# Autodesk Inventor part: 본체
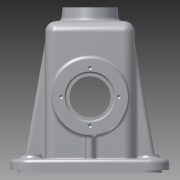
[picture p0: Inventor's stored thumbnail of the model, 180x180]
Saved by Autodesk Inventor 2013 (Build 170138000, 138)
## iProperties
Created: 2016-01
Part Number: 본체
Material: 알루미늄 6061
Document SubType Name: Modeling
Designer: User
Mass: 857.084 g
Surface Area: 924.112 cm^2
Volume: 316.267 cm^3
Density: 2.71 g/cm^3
Author: User
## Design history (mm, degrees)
sketch "스케치1"
  geometry: L1 (-32.5, 32.5)-(32.5, 32.5); L2 (32.5, 32.5)-(32.5, -32.5); L3 (32.5, -32.5)-(-32.5, -32.5); L4 (-32.5, -32.5)-(-32.5, 32.5); L5 (-32.5, 32.5)-(32.5, -32.5); L6 (32.5, 32.5)-(-32.5, -32.5); 1 further point
  constraints: 12 end point, 2 midpoint, 2 parallel, 1 horizontal, 1 perpendicular
  dimensions: "d0" = 65 distance of L2.end L3.end; "d1" = 65 distance of L1.end L2.end
extrude "돌출1" new body sketch "스케치1" distance "d2" = 110; taper "d3" = 0 deg
sketch "스케치2"
  geometry: L1 (-57.5, 65)-(57.5, 65); L2 (57.5, 65)-(57.5, -65); L3 (57.5, -65)-(-57.5, -65); L4 (-57.5, -65)-(-57.5, 65); L5 (-57.5, 65)-(57.5, -65); L6 (57.5, 65)-(-57.5, -65); 1 further point
  constraints: 12 end point, 2 midpoint, 2 parallel, 1 horizontal, 1 perpendicular
  dimensions: "d4" = 115 distance of L2.end L3.end; "d5" = 130 distance of L1.end L2.end
extrude "돌출2" join sketch "스케치2" distance "d6" = 10; taper "d7" = 0 deg
sketch "스케치3"
  geometry: L1 (-57.5, 65)-(57.5, 65) reference; L2 (-57.5, -65)-(-57.5, 65) reference; L3 (57.5, -65)-(-57.5, -65) reference; L4 (57.5, 65)-(57.5, -65) reference; L5 (52.5, 60)-(-52.5, 60); L6 (-52.5, 60)-(-52.5, -60); L7 (-52.5, -60)-(52.5, -60); L8 (52.5, -60)-(52.5, 60); 1 further point
  constraints: 8 end point, 3 other
  dimensions: "d8" = 5 distance between parallel lines of L5 L1
extrude "돌출3" cut sketch "스케치3" distance "d9" = 2; taper "d10" = 0 deg
fillet "모깎기1" dims "d11" = 15
fillet "모깎기2" dims "d12" = 15
sketch "스케치4"
  geometry: L1 (-65, 10)-(-32.5, 10) reference; L2 (-32.5, 10)-(-32.5, 110) reference; L3 (-32.5, 110)-(32.5, 110) reference; L4 (32.5, 110)-(32.5, 10) reference; L5 (32.5, 10)-(65, 10) reference; L6 (65, 10)-(65, 2) reference; L7 (65, 2)-(60, 2) reference; L8 (60, 2)-(60, 0) reference; L9 (60, 0)-(-60, 0) reference; L10 (-60, 0)-(-60, 2) reference; L11 (-60, 2)-(-65, 2) reference; L12 (-65, 2)-(-65, 10) reference; L13 (27.5, 105)-(27.5, 0); L14 (27.5, 105)-(-27.5, 105); L15 (-27.5, 105)-(-27.5, 0); 1 further point
  constraints: 6 end point, 2 perpendicular, 2 point on line, 1 vertical
  dimensions: "d13" = 5 distance between parallel lines of L4 L13; "d14" = 5 distance between parallel lines of L2 L15; "d15" = 5 distance between parallel lines of L3 L14
extrude "돌출4" cut sketch "스케치4" stored distance "d16" = 55; taper "d17" = 0 deg
sketch "스케치5"
  geometry: L1 (0, 0)-(65, 0) reference; L2 (70, -110)-(-5, -110) reference; C1 r 27.5 at (32.5, -55); 2 further points
  constraints: 1 centre point, 1 midpoint, 1 vertical alignment
  dimensions: "d18" = 55 diameter of C1; "d19" = 55 distance from line of L2 C1.centre
extrude "돌출5" join sketch "스케치5" distance "d20" = 15; taper "d21" = 0 deg
sketch "스케치6"
  geometry: L1 (-52.742, 55)-(52.163, 55); L2 (-30.5, 72.5)-(-30.5, 70); L3 (30.5, 70)-(30.5, 72.5); L4 (-65, 10)-(-32.5, 10) reference; L5 (-32.5, 10)-(-32.5, 27.5) reference; L6 (-32.5, 27.5)-(-47.5, 27.5) reference; L7 (-47.5, 27.5)-(-47.5, 82.5) reference; L8 (-47.5, 82.5)-(-32.5, 82.5) reference; L9 (-32.5, 82.5)-(-32.5, 110) reference; L10 (-32.5, 110)-(32.5, 110) reference; L11 (32.5, 110)-(32.5, 82.5) reference; L12 (32.5, 82.5)-(47.5, 82.5) reference; L13 (47.5, 82.5)-(47.5, 27.5) reference; L14 (47.5, 27.5)-(32.5, 27.5) reference; L15 (32.5, 27.5)-(32.5, 10) reference; L16 (32.5, 10)-(65, 10) reference; L17 (65, 10)-(65, 2) reference; L18 (65, 2)-(60, 2) reference; L19 (60, 2)-(60, 0) reference; L20 (60, 0)-(27.5, 0) reference; L21 (27.5, 0)-(27.5, 105) reference; L22 (27.5, 105)-(-27.5, 105) reference; L23 (-27.5, 105)-(-27.5, 0) reference; L24 (-27.5, 0)-(-60, 0) reference; L25 (-60, 0)-(-60, 2) reference; L26 (-60, 2)-(-65, 2) reference; L27 (-65, 2)-(-65, 10) reference; L28 (-30.5, 72.5)-(-47.5, 72.5); L29 (30.5, 72.5)-(47.5, 72.5); L30 (-47.5, 72.5)-(-47.5, 55); L31 (47.5, 72.5)-(47.5, 55); L32 (-30.5, 70)-(-27.5, 70); L33 (-27.5, 70)-(-27.5, 55); L34 (30.5, 72.5)-(30.5, 70); L35 (30.5, 70)-(27.5, 70); L36 (27.5, 70)-(27.5, 55); L37 (-47.5, 55)-(-27.5, 55); L38 (27.5, 55)-(47.5, 55); 1 further point
  constraints: 28 end point, 8 point on line, 4 perpendicular, 2 collinear, 2 midpoint, 2 parallel, 1 horizontal
  dimensions: "d22" = 55 distance from line of point (0, 0) L1; "d23" = 35 diameter of L28 L1; "d25" = 17 distance of L2.start L28.end; "d26" = 17 distance of L3.end L29.end; "d27" = 61 distance between parallel lines of L2 L3; "d28" = 30 diameter of L32 L1
  node "절단 모서리 투영2"
revolve "회전1" stored, may be unused: angle "d29" = 90 deg
revolve "회전2" stored, may be unused: angle "d30" = 90 deg
sketch "스케치7"
  geometry: C1 r 20 at (0, 0); 1 further point
  constraints: 1 centre point, 1 coincident
  dimensions: "d31" = 40 diameter of C1
extrude "돌출6" join sketch "스케치7" distance "d32" = 10; taper "d33" = 0 deg
feature "면 기울기1" dims angle "d34" = 5 deg
sketch "스케치8"
  geometry: C1 r 20 at (0, 0) reference; C2 r 10.5 at (0, 0)
  constraints: 1 centre point, 1 coincident
  dimensions: "d35" = 21 diameter of C2
extrude "돌출7" cut sketch "스케치8" distance "d36" = 20.75; taper "d37" = 0 deg
sketch "스케치9" dims "d38" = 29
  geometry: C1 r 20 at (0, 0) reference; 2 further points
  constraints: 2 vertical alignment, 1 coincident, 2 other
hole "구멍1" sketch "스케치9" at (0, 14.5) diameter "d39" = 2.459; stored, may be unused: countersink angle "d43" = 90 deg, drill point angle "d45" = 118 deg; dims "d40" = 7, "d41" = 4, "d42" = 2, "d44" = 9
sketch "스케치10" dims "d49" = 42
  geometry: C1 r 27.5 at (0, 0) reference; 3 further points
  constraints: 2 horizontal alignment, 1 coincident, 2 other
hole "구멍2" sketch "스케치10" at (21, 0) diameter "d50" = 3.242; stored, may be unused: countersink angle "d54" = 90 deg, drill point angle "d56" = 118 deg; dims "d51" = 8, "d52" = 4, "d53" = 2, "d55" = 10
sketch "스케치11"
  geometry: L1 (27.5, 0)-(27.5, 105) reference; L2 (27.5, 105)-(10.5, 105) reference; L3 (10.5, 105)-(10.5, 120) reference; L4 (10.5, 120)-(13.27, 120) reference; L5 (13.27, 120)-(13.27, 111) reference; L6 (13.27, 111)-(14.5, 110.261) reference; L7 (14.5, 110.261)-(15.73, 111) reference; L8 (15.73, 111)-(15.73, 120) reference; L9 (15.73, 120)-(20, 120) reference; L10 (20, 120)-(20.875, 110) reference; L11 (20.875, 110)-(32.5, 110) reference; L12 (32.5, 110)-(32.5, 10) reference; L13 (32.5, 10)-(57.5, 10) reference; L14 (57.5, 10)-(57.5, 2) reference; L15 (57.5, 2)-(52.5, 2) reference; L16 (52.5, 2)-(52.5, 0) reference; L17 (52.5, 0)-(27.5, 0) reference; L18 (-52.5, 2)-(-57.5, 2) reference; L19 (-57.5, 2)-(-57.5, 10) reference; L20 (-57.5, 10)-(-32.5, 10) reference; L21 (-32.5, 10)-(-32.5, 110) reference; L22 (-32.5, 110)-(-20.875, 110) reference; L23 (-20.875, 110)-(-20, 120) reference; L24 (-20, 120)-(-15.73, 120) reference; L25 (-15.73, 120)-(-15.73, 111) reference; L26 (-15.73, 111)-(-14.5, 110.261) reference; L27 (-14.5, 110.261)-(-13.27, 111) reference; L28 (-13.27, 111)-(-13.27, 120) reference; L29 (-13.27, 120)-(-10.5, 120) reference; L30 (-10.5, 120)-(-10.5, 105) reference; L31 (-10.5, 105)-(-27.5, 105) reference; L32 (-27.5, 105)-(-27.5, 0) reference; L33 (-27.5, 0)-(-52.5, 0) reference; L34 (-52.5, 0)-(-52.5, 2) reference; L35 (-32.5, 95.069)-(-47.5, 10); L36 (47.5, 10)-(32.5, 95.069); 1 further point
  constraints: 4 end point, 4 point on line
  dimensions: "d60" = 10 deg angle of L35 L19; "d61" = 10 distance from line of L35.end L19; "d62" = 10 distance of L13.end L36.start; "d63" = 10 deg angle of L14 L36
  node "절단 모서리 투영3"
feature "리브1" dims "d64" = 1, "d65" = 10, "d66" = 0, "d67" = 0, "d68" = 1, "d69" = 1
feature "리브2" dims "d70" = 1, "d71" = 10, "d72" = 0, "d73" = 0, "d74" = 1, "d75" = 1
sketch "스케치12"
  geometry: L1 (-52.5, 45)-(-52.5, -45) reference; L2 (37.5, 60)-(-37.5, 60) reference; L3 (-27.5, 27.5)-(27.5, 27.5) reference; L4 (-42.5, 50)-(42.5, 50); L5 (-42.5, 50)-(-42.5, -50); C1 r 3 at (-42.5, 50); C2 r 3 at (42.5, 50); C3 r 3 at (-42.5, -50); C4 r 3 at (42.5, -50); 5 further points
  constraints: 4 centre point, 4 end point, 4 midpoint, 3 vertical alignment, 2 horizontal alignment, 1 parallel, 1 perpendicular
  dimensions: "d76" = 6 diameter of C2; "d77" = 6 diameter of C1; "d78" = 6 diameter of C3; "d79" = 6 diameter of C4; "d80" = 85 distance of L4.end L4.start; "d81" = 100 distance of L5.end L4.start
sketch "스케치13"
  geometry: C1 r 3 at (-42.5, -50) reference; C2 r 3 at (-42.5, 50) reference; C3 r 3 at (42.5, 50) reference; C4 r 3 at (42.5, -50) reference; C5 r 7.5 at (-42.5, -50); C6 r 7.5 at (42.5, -50); C7 r 7.5 at (-42.5, 50); C8 r 7.5 at (42.5, 50); 1 further point
  constraints: 4 centre point, 4 coincident
  dimensions: "d82" = 15 diameter of C5; "d83" = 15 diameter of C6; "d84" = 15 diameter of C7; "d85" = 15 diameter of C8
extrude "돌출8" join sketch "스케치13" distance "d86" = 3; taper "d87" = 0 deg
hole "구멍3" sketch "스케치12" diameter "d88" = 6; stored, may be unused: countersink angle "d92" = 90 deg, drill point angle "d94" = 118 deg; dims "d89" = 8, "d90" = 4, "d91" = 2, "d93" = 10
chamfer "모따기1" distance "d95" = 1; stored, may be unused: second distance "d96" = 2, angle "d97" = 45 deg
fillet "모깎기3" dims "d98" = 8
fillet "모깎기4" dims "d99" = 8
sketch "스케치14"
  geometry: L1 (30.5, 70)-(27.5, 70) reference; L2 (27.5, 70)-(27.5, 105) reference; L3 (27.5, 105)-(10.5, 105) reference; L4 (10.5, 105)-(10.5, 119) reference; L5 (10.5, 119)-(11.5, 120) reference; L6 (11.5, 120)-(13.27, 120) reference; L7 (13.27, 120)-(13.27, 111) reference; L8 (13.27, 111)-(14.5, 110.261) reference; L9 (14.5, 110.261)-(15.73, 111) reference; L10 (15.73, 111)-(15.73, 120) reference; L11 (15.73, 120)-(20, 120) reference; L12 (20, 120)-(20.875, 110) reference; L13 (20.875, 110)-(24.5, 110) reference; L14 (32.5, 102)-(32.5, 82.5) reference; L15 (32.5, 82.5)-(47.5, 82.5) reference; L16 (47.5, 82.5)-(47.5, 77.621) reference; L17 (47.5, 77.621)-(37.5, 77.621) reference; L18 (37.5, 77.621)-(36.526, 76) reference; L19 (36.526, 76)-(37.5, 74.379) reference; L20 (37.5, 74.379)-(47.5, 74.379) reference; L21 (47.5, 74.379)-(47.5, 73.5) reference; L22 (47.5, 73.5)-(46.5, 72.5) reference; L23 (46.5, 72.5)-(30.5, 72.5) reference; L24 (30.5, 72.5)-(30.5, 70) reference; L25 (27.5, 40)-(30.5, 40) reference; L26 (30.5, 40)-(30.5, 37.5) reference; L27 (30.5, 37.5)-(46.5, 37.5) reference; L28 (46.5, 37.5)-(47.5, 36.5) reference; L29 (47.5, 36.5)-(47.5, 35.621) reference; L30 (47.5, 35.621)-(37.5, 35.621) reference; L31 (37.5, 35.621)-(36.526, 34) reference; L32 (36.526, 34)-(37.5, 32.379) reference; L33 (37.5, 32.379)-(47.5, 32.379) reference; L34 (47.5, 32.379)-(47.5, 27.5) reference; L35 (47.5, 27.5)-(32.5, 27.5) reference; L36 (32.5, 27.5)-(32.5, 10) reference; L37 (32.5, 10)-(65, 10) reference; L38 (65, 10)-(65, 2) reference; L39 (65, 2)-(60, 2) reference; L40 (60, 2)-(60, 0) reference; L41 (60, 0)-(27.5, 0) reference; L42 (27.5, 0)-(27.5, 40) reference; L43 (-27.5, 70)-(-30.5, 70) reference; L44 (-30.5, 70)-(-30.5, 72.5) reference; L45 (-30.5, 72.5)-(-46.5, 72.5) reference; L46 (-46.5, 72.5)-(-47.5, 73.5) reference; L47 (-47.5, 73.5)-(-47.5, 74.379) reference; L48 (-47.5, 74.379)-(-37.5, 74.379) reference; L49 (-37.5, 74.379)-(-36.526, 76) reference; L50 (-36.526, 76)-(-37.5, 77.621) reference; L51 (-37.5, 77.621)-(-47.5, 77.621) reference; L52 (-47.5, 77.621)-(-47.5, 82.5) reference; L53 (-47.5, 82.5)-(-32.5, 82.5) reference; L54 (-32.5, 82.5)-(-32.5, 102) reference; L55 (-24.5, 110)-(-20.875, 110) reference; L56 (-20.875, 110)-(-20, 120) reference; L57 (-20, 120)-(-15.73, 120) reference; L58 (-15.73, 120)-(-15.73, 111) reference; L59 (-15.73, 111)-(-14.5, 110.261) reference; L60 (-14.5, 110.261)-(-13.27, 111) reference; L61 (-13.27, 111)-(-13.27, 120) reference; L62 (-13.27, 120)-(-11.5, 120) reference; L63 (-11.5, 120)-(-10.5, 119) reference; L64 (-10.5, 119)-(-10.5, 105) reference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; A1 r 8 centre (24.5, 102) between (32.5, 102) and (24.5, 110) reference; A2 r 8 centre (-24.5, 102) between (-24.5, 110) and (-32.5, 102) reference; 1 further point
  constraints: 4 end point, 4 point on line, 2 parallel
  dimensions: "d100" = 15 distance between parallel lines of L68 L85; "d101" = 15 distance between parallel lines of L86 L42
  node "절단 모서리 투영4"
feature "리브3" dims "d102" = 1, "d103" = 6, "d104" = 0, "d105" = 0, "d106" = 1, "d107" = 1
feature "리브4" dims "d108" = 1, "d109" = 6, "d110" = 0, "d111" = 0, "d112" = 1, "d113" = 1
fillet "모깎기5" dims "d114" = 3
fillet "모깎기6" dims "d115" = 3
fillet "모깎기7" dims "d116" = 3
fillet "모깎기8" dims "d117" = 3
fillet "모깎기9" dims "d118" = 3
sketch "스케치15"
  geometry: L1 (57, 0)-(57, 92) reference; L2 (4.5, -18)-(44.5, -18) reference; 3 further points
  constraints: 1 other
  dimensions: "d120" = 32.5 distance from line of point (24.5, 8) L1; "d121" = 26 distance from line of point (24.5, 8) L2
feature "엠보싱1" sketch "스케치15" dims "d122" = 0.5, "d123" = 0
fillet "모깎기11" dims "d124" = 3
fillet "모깎기12" dims "d125" = 0.3
fillet "모깎기13" dims "d126" = 1
node "솔리드1"
mirror "대칭1"
pattern_circular "원형 패턴1" dims angle "d47" = 360 deg
pattern_circular "원형 패턴2" dims angle "d58" = 360 deg
mirror "대칭2"
node "절단 모서리 투영1"
